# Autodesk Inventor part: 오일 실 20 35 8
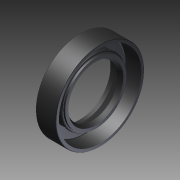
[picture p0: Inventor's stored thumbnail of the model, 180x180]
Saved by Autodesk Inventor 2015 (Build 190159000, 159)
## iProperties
Created: 2026-04
Part Number: 오일 실 20 35 8
Material: 일반
Document SubType Name: Modeling
Designer: User
Density: 1 g/cm^3
Appearance: 기본값
Author: User
Author: jhkim
Description: 오일-실
Creation Date: 2026-03-26
Sending System: Autodesk Inventor 2026
Preprocessor: ST-DEVELOPER v20.1
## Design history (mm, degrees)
node "오일 실 20 35 81"
body "Solid1"
node "기준1"
